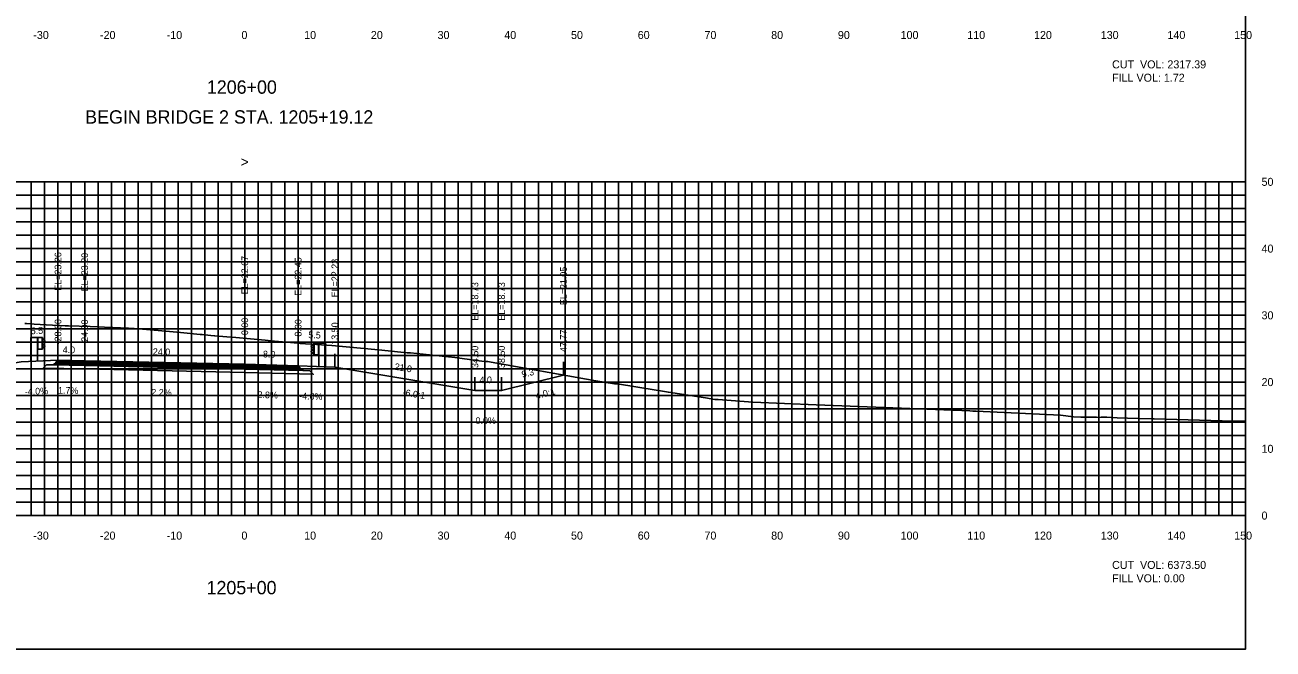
# Model space of a CAD drawing. Extents: x 1797305 to 1804485, y 245831 to 250849.
# Drawn here: x 1802938.1 to 1803125.1, y 250079.4 to 250172.9 of the extents above; entities that cross this region are included whole.
import ezdxf

# ---------------------------------------------------------------- set-up
doc = ezdxf.new("R2010")
doc.units = 0
for name, color, linetype in [('1', 7, 'Continuous'), ('10', 7, 'Continuous'), ('29', 7, 'Continuous'), ('60', 7, 'Continuous'), ('ALIGN-CARP', 7, 'Continuous'), ('BASE', 7, 'Continuous'), ('CL-CNST', 7, 'Continuous'), ('EDPV-LINE', 7, 'Continuous'), ('Level 31', 7, 'Continuous'), ('Level 62', 7, 'Continuous'), ('LIMT-CSLINE', 7, 'Continuous'), ('M-ROADS', 7, 'Continuous'), ('SHDR-UPAV', 7, 'Continuous'), ('SURVEY - DRAINAGE - Area Shapes', 7, 'Continuous'), ('SURVEY - DRAINAGE - Bridge Hydraulic Data - Points - Locators', 7, 'Continuous')]:
    doc.layers.add(name, color=color, linetype=linetype)

msp = doc.modelspace()

# ---------------------------------------------------------------- linework, layer by layer
for p, q in [((1802943, 250122.7), (1802943, 250124.7)), ((1802947, 250122.63), (1802947, 250124.63)), ((1802971, 250122.1), (1802971, 250124.1)), ((1802979, 250121.88), (1802979, 250123.88)), ((1802984.5, 250121.66), (1802984.5, 250123.66)), ((1803018.77, 250120.48), (1803018.77, 250122.48)), ((1803005.5, 250118.16), (1803005.5, 250120.16)), ((1803009.5, 250118.16), (1803009.5, 250120.16))]:
    msp.add_line(p, q)
msp.add_lwpolyline([(1802821, 250079.43), (1803121, 250079.43), (1803121, 250269.43), (1802821, 250269.43)], close=True)
at = {"layer": '29'}
for p, q in [((1802821, 250149.43), (1803121, 250149.43)), ((1802939, 250099.43), (1802939, 250149.43)), ((1802941, 250099.43), (1802941, 250149.43)), ((1802943, 250099.43), (1802943, 250149.43)), ((1802945, 250099.43), (1802945, 250149.43)), ((1802947, 250099.43), (1802947, 250149.43)), ((1802949, 250099.43), (1802949, 250149.43)), ((1802951, 250099.43), (1802951, 250149.43)), ((1802953, 250099.43), (1802953, 250149.43)), ((1802955, 250099.43), (1802955, 250149.43)), ((1802957, 250099.43), (1802957, 250149.43)), ((1802959, 250099.43), (1802959, 250149.43)), ((1802961, 250099.43), (1802961, 250149.43)), ((1802963, 250099.43), (1802963, 250149.43)), ((1802965, 250099.43), (1802965, 250149.43)), ((1802967, 250099.43), (1802967, 250149.43)), ((1802969, 250099.43), (1802969, 250149.43)), ((1802971, 250099.43), (1802971, 250149.43)), ((1802973, 250099.43), (1802973, 250149.43)), ((1802975, 250099.43), (1802975, 250149.43)), ((1802977, 250099.43), (1802977, 250149.43)), ((1802979, 250099.43), (1802979, 250149.43)), ((1802981, 250099.43), (1802981, 250149.43)), ((1802983, 250099.43), (1802983, 250149.43)), ((1802985, 250099.43), (1802985, 250149.43)), ((1802987, 250099.43), (1802987, 250149.43)), ((1802989, 250099.43), (1802989, 250149.43)), ((1802991, 250099.43), (1802991, 250149.43)), ((1802993, 250099.43), (1802993, 250149.43)), ((1802995, 250099.43), (1802995, 250149.43)), ((1802997, 250099.43), (1802997, 250149.43)), ((1802999, 250099.43), (1802999, 250149.43)), ((1803001, 250099.43), (1803001, 250149.43)), ((1803003, 250099.43), (1803003, 250149.43)), ((1803005, 250099.43), (1803005, 250149.43)), ((1803007, 250099.43), (1803007, 250149.43)), ((1803009, 250099.43), (1803009, 250149.43)), ((1803011, 250099.43), (1803011, 250149.43)), ((1803013, 250099.43), (1803013, 250149.43)), ((1803015, 250099.43), (1803015, 250149.43)), ((1803017, 250099.43), (1803017, 250149.43)), ((1803019, 250099.43), (1803019, 250149.43)), ((1803021, 250099.43), (1803021, 250149.43)), ((1803023, 250099.43), (1803023, 250149.43)), ((1803025, 250099.43), (1803025, 250149.43)), ((1803027, 250099.43), (1803027, 250149.43)), ((1803029, 250099.43), (1803029, 250149.43)), ((1803031, 250099.43), (1803031, 250149.43)), ((1803033, 250099.43), (1803033, 250149.43)), ((1803035, 250099.43), (1803035, 250149.43)), ((1803037, 250099.43), (1803037, 250149.43)), ((1803039, 250099.43), (1803039, 250149.43)), ((1803041, 250099.43), (1803041, 250149.43)), ((1803043, 250099.43), (1803043, 250149.43)), ((1803045, 250099.43), (1803045, 250149.43)), ((1803047, 250099.43), (1803047, 250149.43)), ((1803049, 250099.43), (1803049, 250149.43)), ((1803051, 250099.43), (1803051, 250149.43)), ((1803053, 250099.43), (1803053, 250149.43)), ((1803055, 250099.43), (1803055, 250149.43)), ((1803057, 250099.43), (1803057, 250149.43)), ((1803059, 250099.43), (1803059, 250149.43)), ((1803061, 250099.43), (1803061, 250149.43)), ((1803063, 250099.43), (1803063, 250149.43)), ((1803065, 250099.43), (1803065, 250149.43)), ((1803067, 250099.43), (1803067, 250149.43)), ((1803069, 250099.43), (1803069, 250149.43)), ((1803071, 250099.43), (1803071, 250149.43)), ((1803073, 250099.43), (1803073, 250149.43)), ((1803075, 250099.43), (1803075, 250149.43)), ((1803077, 250099.43), (1803077, 250149.43)), ((1803079, 250099.43), (1803079, 250149.43)), ((1803081, 250099.43), (1803081, 250149.43)), ((1803083, 250099.43), (1803083, 250149.43)), ((1803085, 250099.43), (1803085, 250149.43)), ((1803087, 250099.43), (1803087, 250149.43)), ((1803089, 250099.43), (1803089, 250149.43)), ((1803091, 250099.43), (1803091, 250149.43)), ((1803093, 250099.43), (1803093, 250149.43)), ((1803095, 250099.43), (1803095, 250149.43)), ((1803097, 250099.43), (1803097, 250149.43)), ((1803099, 250099.43), (1803099, 250149.43)), ((1803101, 250099.43), (1803101, 250149.43)), ((1803103, 250099.43), (1803103, 250149.43)), ((1803105, 250099.43), (1803105, 250149.43)), ((1803107, 250099.43), (1803107, 250149.43)), ((1803109, 250099.43), (1803109, 250149.43)), ((1803111, 250099.43), (1803111, 250149.43)), ((1803113, 250099.43), (1803113, 250149.43)), ((1803115, 250099.43), (1803115, 250149.43)), ((1803117, 250099.43), (1803117, 250149.43)), ((1803119, 250099.43), (1803119, 250149.43)), ((1803121, 250099.43), (1803121, 250149.43)), ((1802821, 250147.43), (1803121, 250147.43)), ((1802821, 250145.43), (1803121, 250145.43)), ((1802821, 250143.43), (1803121, 250143.43)), ((1802821, 250141.43), (1803121, 250141.43)), ((1802821, 250139.43), (1803121, 250139.43)), ((1802821, 250137.43), (1803121, 250137.43)), ((1802821, 250135.43), (1803121, 250135.43)), ((1802821, 250133.43), (1803121, 250133.43)), ((1802821, 250131.43), (1803121, 250131.43)), ((1802821, 250129.43), (1803121, 250129.43)), ((1802821, 250127.43), (1803121, 250127.43)), ((1802821, 250125.43), (1803121, 250125.43)), ((1802821, 250123.43), (1803121, 250123.43)), ((1802821, 250121.43), (1803121, 250121.43)), ((1802821, 250119.43), (1803121, 250119.43)), ((1802821, 250117.43), (1803121, 250117.43)), ((1802821, 250115.43), (1803121, 250115.43)), ((1802821, 250113.43), (1803121, 250113.43)), ((1802821, 250111.43), (1803121, 250111.43)), ((1802821, 250109.43), (1803121, 250109.43)), ((1802821, 250107.43), (1803121, 250107.43)), ((1802821, 250105.43), (1803121, 250105.43)), ((1802821, 250103.43), (1803121, 250103.43)), ((1802821, 250101.43), (1803121, 250101.43)), ((1802821, 250099.43), (1803121, 250099.43))]:
    msp.add_line(p, q, dxfattribs=at)
at = {"layer": 'ALIGN-CARP'}
msp.add_lwpolyline([(1802941.29, 250122), (1802942.29, 250121.99), (1802947, 250121.91), (1802971, 250121.38), (1802979.74, 250121.14), (1802980.74, 250121.11), (1802981.26, 250120.6), (1802971, 250120.88), (1802947, 250121.41), (1802940.8, 250121.51)], close=True, dxfattribs=at)
at = {"layer": 'CL-CNST'}
msp.add_lwpolyline([(1802838.47, 250126.38), (1802912.5, 250118.98), (1802916.5, 250118.98), (1802937.5, 250122.48), (1802943, 250122.7), (1802947, 250122.63), (1802971, 250122.1), (1802979, 250121.88), (1802984.5, 250121.66), (1803005.5, 250118.16), (1803009.5, 250118.16), (1803018.77, 250120.48)], dxfattribs=at)
at = {"layer": 'Level 31'}
for p, q in [((1803121, 250099.43), (1803121, 250149.43)), ((1803121.06, 250149.43), (1803121, 250149.43)), ((1803121.06, 250139.43), (1803121, 250139.43)), ((1803121.06, 250129.43), (1803121, 250129.43)), ((1803121.06, 250119.43), (1803121, 250119.43)), ((1803121.06, 250109.43), (1803121, 250109.43)), ((1802821, 250099.43), (1803121, 250099.43)), ((1802941, 250099.37), (1802941, 250099.43)), ((1802951, 250099.37), (1802951, 250099.43)), ((1802961, 250099.37), (1802961, 250099.43)), ((1802971, 250099.37), (1802971, 250099.43)), ((1802981, 250099.37), (1802981, 250099.43)), ((1802991, 250099.37), (1802991, 250099.43)), ((1803001, 250099.37), (1803001, 250099.43)), ((1803011, 250099.37), (1803011, 250099.43)), ((1803021, 250099.37), (1803021, 250099.43)), ((1803031, 250099.37), (1803031, 250099.43)), ((1803041, 250099.37), (1803041, 250099.43)), ((1803051, 250099.37), (1803051, 250099.43)), ((1803061, 250099.37), (1803061, 250099.43)), ((1803071, 250099.37), (1803071, 250099.43)), ((1803081, 250099.37), (1803081, 250099.43)), ((1803091, 250099.37), (1803091, 250099.43)), ((1803101, 250099.37), (1803101, 250099.43)), ((1803111, 250099.37), (1803111, 250099.43)), ((1803121, 250099.37), (1803121, 250099.43)), ((1803121.06, 250099.43), (1803121, 250099.43))]:
    msp.add_line(p, q, dxfattribs=at)
at = {"layer": 'Level 62'}
msp.add_lwpolyline([(1802979.35, 250121.53), (1802979.16, 250121.72), (1802971, 250121.95), (1802947, 250122.48), (1802942.85, 250122.55), (1802942.67, 250122.36), (1802947, 250122.29), (1802971, 250121.76)], close=True, dxfattribs=at)
at = {"layer": 'LIMT-CSLINE'}
msp.add_line((1802941, 250120.82), (1802941, 250109.99), dxfattribs=at)
at = {"layer": 'M-ROADS'}
msp.add_lwpolyline([(1802938.02, 250128.19), (1802938.29, 250128.19), (1802939.43, 250128.12), (1802941.23, 250128.02), (1802944.09, 250127.86), (1802944.46, 250127.85), (1802944.59, 250127.84), (1802947.81, 250127.74), (1802949.96, 250127.66), (1802951.24, 250127.62), (1802953.55, 250127.53), (1802954.42, 250127.45), (1802954.75, 250127.42), (1802955.07, 250127.4), (1802955.08, 250127.39), (1802958.01, 250127.14), (1802959.7, 250126.99), (1802961.37, 250126.84), (1802964.31, 250126.58), (1802964.63, 250126.55), (1802965.9, 250126.43), (1802966.48, 250126.38), (1802966.5, 250126.38), (1802968.32, 250126.22), (1802969.13, 250126.15), (1802971.88, 250125.9), (1802974.07, 250125.7), (1802975.47, 250125.58), (1802977.25, 250125.42), (1802977.26, 250125.41), (1802979.01, 250125.25), (1802979.09, 250125.25), (1802979.29, 250125.23), (1802981.74, 250125.06), (1802984.04, 250124.9), (1802991.03, 250124.24), (1802995.36, 250123.8), (1802995.82, 250123.79), (1803002.47, 250123.1), (1803006.9, 250122.52), (1803007.25, 250122.52), (1803007.4, 250122.52), (1803023.63, 250119.61), (1803026.43, 250119.17), (1803026.87, 250119.17), (1803032.66, 250118.22), (1803033.62, 250118.05), (1803034.5, 250117.9), (1803040.05, 250117.06), (1803041.46, 250116.8), (1803041.86, 250116.8), (1803041.95, 250116.8), (1803047.16, 250116.4), (1803056.65, 250116.01), (1803077.1, 250115.22), (1803077.27, 250115.21), (1803079.7, 250115.11), (1803080.11, 250115.09), (1803080.6, 250115.09), (1803080.63, 250115.09), (1803093.26, 250114.45), (1803095.22, 250114.23), (1803096.32, 250114.16), (1803098.65, 250114.19), (1803099, 250114.14), (1803099.36, 250114.19), (1803100.23, 250114.15), (1803100.87, 250114.11), (1803101.78, 250114.08), (1803103.32, 250114.03), (1803106.98, 250113.92), (1803107.31, 250113.92), (1803117.48, 250113.6), (1803119.15, 250113.55), (1803119.74, 250113.57), (1803120.56, 250113.59), (1803121, 250113.56)], dxfattribs=at)
at = {"layer": 'SHDR-UPAV'}
for p, q in [((1802938.91, 250126.1), (1802938.91, 250122.53)), ((1802938.91, 250126.1), (1802940.66, 250126.1)), ((1802939.91, 250126.1), (1802939.91, 250122.57)), ((1802939.91, 250124.35), (1802940.66, 250124.35)), ((1802939.96, 250126.1), (1802939.96, 250124.35)), ((1802940.61, 250126.1), (1802940.61, 250124.35)), ((1802940.66, 250126.1), (1802940.66, 250124.35)), ((1802940.66, 250125.95), (1802941.03, 250125.65)), ((1802941.03, 250125.58), (1802940.66, 250125.29)), ((1802940.66, 250125.15), (1802941.03, 250124.85)), ((1802941.03, 250124.78), (1802940.66, 250124.5)), ((1802981.34, 250125.13), (1802980.97, 250124.83)), ((1802980.97, 250124.76), (1802981.34, 250124.48)), ((1802981.34, 250124.34), (1802980.97, 250124.04)), ((1802981.34, 250125.28), (1802981.34, 250123.53)), ((1802983.09, 250125.28), (1802981.34, 250125.28)), ((1802981.39, 250125.28), (1802981.39, 250123.53)), ((1802982.04, 250125.28), (1802982.04, 250123.53)), ((1802982.09, 250125.28), (1802982.09, 250121.76)), ((1802983.09, 250125.28), (1802983.09, 250121.72)), ((1802980.97, 250123.97), (1802981.34, 250123.68)), ((1802982.09, 250123.53), (1802981.34, 250123.53))]:
    msp.add_line(p, q, dxfattribs=at)
for centre, start, end in [((1802941, 250125.61), 313.3792, 45), ((1802941, 250124.82), 313.3792, 45), ((1802981.01, 250124.8), 135, 226.6208), ((1802981.01, 250124), 135, 226.6208)]:
    msp.add_arc(centre, 0.05, start, end, dxfattribs=at)
at = {"layer": 'SURVEY - DRAINAGE - Area Shapes'}
msp.add_lwpolyline([(1802979.16, 250121.72), (1802979, 250121.88), (1802971, 250122.1), (1802947, 250122.63), (1802943, 250122.7), (1802942.85, 250122.55), (1802947, 250122.48), (1802971, 250121.95)], close=True, dxfattribs=at)
at = {"layer": 'SURVEY - DRAINAGE - Bridge Hydraulic Data - Points - Locators'}
for points in [[(1802947, 250122.1), (1802971, 250121.57), (1802979.55, 250121.33), (1802979.74, 250121.14), (1802971, 250121.38), (1802947, 250121.91), (1802942.29, 250121.99), (1802942.48, 250122.17)], [(1802947, 250122.29), (1802971, 250121.76), (1802979.35, 250121.53), (1802979.55, 250121.33), (1802971, 250121.57), (1802947, 250122.1), (1802942.48, 250122.17), (1802942.67, 250122.36)]]:
    msp.add_lwpolyline(points, close=True, dxfattribs=at)

# ---------------------------------------------------------------- texts
for s, rotation, p in [('-6.0:1', 350.5377, (1802994.59, 250117.44)), ('4.0:1', 14.0362, (1803014.74, 250116.89))]:
    msp.add_text(s, height=1, rotation=rotation).set_placement(p)
at = {"layer": '1'}
for s, p in [('1206+00', (1802965.32, 250162.63)), ('BEGIN BRIDGE 2 STA. 1205+19.12', (1802947.08, 250158.15)), ('1205+00', (1802965.27, 250087.63))]:
    msp.add_text(s, height=2, dxfattribs=at).set_placement(p)
at = {"layer": '10'}
for s, p in [('-30', (1802939.3, 250170.83)), ('-20', (1802949.3, 250170.83)), ('-10', (1802959.3, 250170.83)), ('0', (1802970.5, 250170.83)), ('10', (1802979.9, 250170.83)), ('20', (1802989.9, 250170.83)), ('30', (1802999.9, 250170.83)), ('40', (1803009.9, 250170.83)), ('50', (1803019.9, 250170.83)), ('60', (1803029.9, 250170.83)), ('70', (1803039.9, 250170.83)), ('80', (1803049.9, 250170.83)), ('90', (1803059.9, 250170.83)), ('100', (1803069.3, 250170.83)), ('110', (1803079.3, 250170.83)), ('120', (1803089.3, 250170.83)), ('130', (1803099.3, 250170.83)), ('140', (1803109.3, 250170.83)), ('150', (1803119.3, 250170.83)), ('-30', (1802939.3, 250095.83)), ('-20', (1802949.3, 250095.83)), ('-10', (1802959.3, 250095.83)), ('0', (1802970.5, 250095.83)), ('10', (1802979.9, 250095.83)), ('20', (1802989.9, 250095.83)), ('30', (1802999.9, 250095.83)), ('40', (1803009.9, 250095.83)), ('50', (1803019.9, 250095.83)), ('60', (1803029.9, 250095.83)), ('70', (1803039.9, 250095.83)), ('80', (1803049.9, 250095.83)), ('90', (1803059.9, 250095.83)), ('100', (1803069.3, 250095.83)), ('110', (1803079.3, 250095.83)), ('120', (1803089.3, 250095.83)), ('130', (1803099.3, 250095.83)), ('140', (1803109.3, 250095.83)), ('150', (1803119.3, 250095.83))]:
    msp.add_text(s, height=1.2, dxfattribs=at).set_placement(p)
at = {"layer": '60'}
for s, p in [('50', (1803123.4, 250148.83)), ('40', (1803123.4, 250138.83)), ('30', (1803123.4, 250128.83)), ('20', (1803123.4, 250118.83)), ('10', (1803123.4, 250108.83)), ('0', (1803123.4, 250098.83))]:
    msp.add_text(s, height=1.2, dxfattribs=at).set_placement(p)
at = {"layer": 'BASE'}
for s, rotation, p in [('5.5', 2.2906, (1802938.93, 250126.59)), ('5.5', 357.7094, (1802980.51, 250126.02)), ('4.0', 359.038, (1802943.7, 250123.78)), ('24.0', 358.7397, (1802957.21, 250123.5)), ('8.0', 358.4116, (1802973.71, 250123.13)), ('21.0', 350.5377, (1802993.39, 250121.29)), ('9.3', 14.0362, (1803012.63, 250120.07)), ('1.7%', 359.038, (1802943, 250117.7)), ('-4.0%', 2.2906, (1802938.04, 250117.49)), ('2.2%', 358.7397, (1802956.98, 250117.41)), ('-2.8%', 358.4116, (1802972.45, 250117.06)), ('-4.0%', 357.7094, (1802979.14, 250116.87))]:
    msp.add_text(s, height=1, rotation=rotation, dxfattribs=at).set_placement(p)
for s, p in [('4.0', (1803006.18, 250119.26)), ('0.0%', (1803005.59, 250113.16))]:
    msp.add_text(s, height=1, dxfattribs=at).set_placement(p)
at = {"layer": 'EDPV-LINE'}
for s, p in [('CUT  VOL: 2317.39', (1803101, 250166.43)), ('FILL VOL: 1.72', (1803101, 250164.43)), ('CUT  VOL: 6373.50', (1803101, 250091.43)), ('FILL VOL: 0.00', (1803101, 250089.43))]:
    msp.add_text(s, height=1.2, dxfattribs=at).set_placement(p)
at = {"layer": 'Level 31'}
msp.add_text('>', height=1.5, dxfattribs=at).set_placement((1802970.39, 250151.68))
at = {"layer": 'LIMT-CSLINE'}
for s, p in [('EL=23.26', (1802943.5, 250133.12)), ('EL=23.20', (1802947.5, 250133.02)), ('EL=22.67', (1802971.5, 250132.57)), ('EL=22.45', (1802979.5, 250132.35)), ('EL=22.23', (1802985, 250132.13)), ('EL=21.05', (1803019.27, 250130.95)), ('EL=18.73', (1803006, 250128.63)), ('EL=18.73', (1803010, 250128.63)), ('-28.00', (1802943.5, 250125.07)), ('-24.00', (1802947.5, 250125.01)), ('0.00', (1802971.5, 250126.46)), ('8.00', (1802979.5, 250126.24)), ('13.50', (1802985, 250125.03)), ('47.77', (1803019.27, 250123.93)), ('34.50', (1803006, 250121.53)), ('38.50', (1803010, 250121.53))]:
    msp.add_text(s, height=1, rotation=90, dxfattribs=at).set_placement(p)

doc.saveas('drawing.dxf')
